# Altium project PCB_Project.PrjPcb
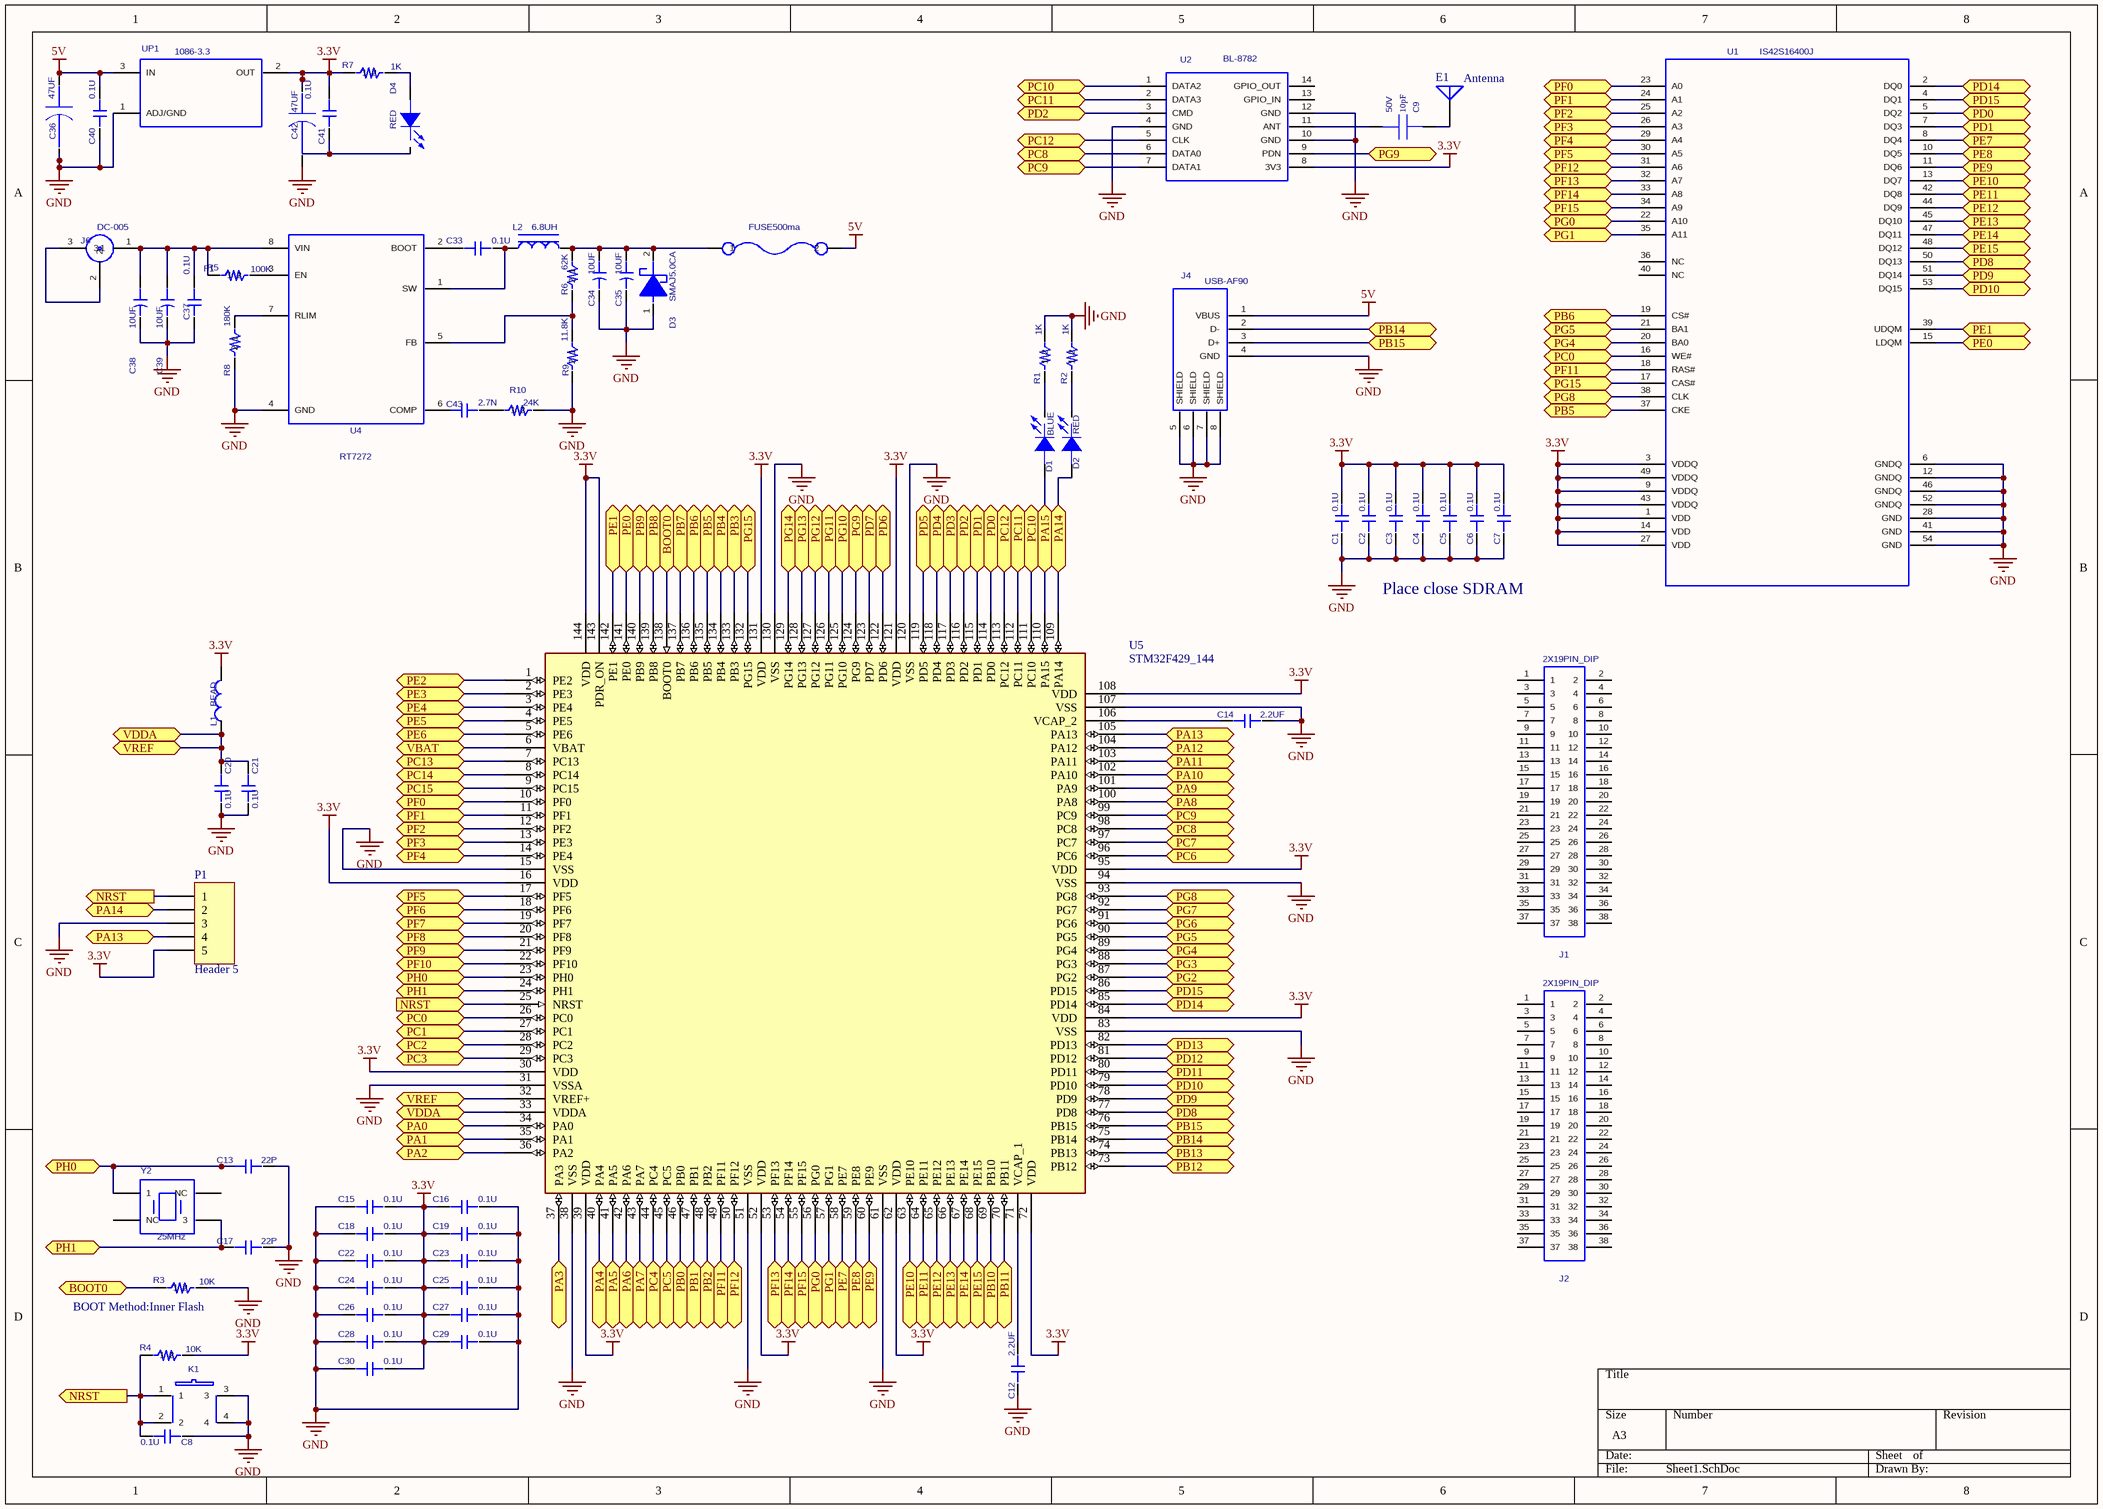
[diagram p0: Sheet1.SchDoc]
1 sheet, 69 parts. Net scope: flat (ports and power ports of the same name join across sheets).
Board files: e3.PcbDoc, Core3.PcbDoc, Core23.PcbDoc, PCB1.PcbDoc, NEW.PcbDoc

## Sheet Sheet1.SchDoc
size A3; DrawnBy: MARS

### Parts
C1  value 0.1U  [C_0603]  (hidden comment: C_0.1UF_0603)
C2  value 0.1U  [C_0603]  (hidden comment: C_0.1UF_0603)
C3  value 0.1U  [C_0603]  (hidden comment: C_0.1UF_0603)
C4  value 0.1U  [C_0603]  (hidden comment: C_0.1UF_0603)
C5  value 0.1U  [C_0603]  (hidden comment: C_0.1UF_0603)
C6  value 0.1U  [C_0603]  (hidden comment: C_0.1UF_0603)
C7  value 0.1U  [C_0603]  (hidden comment: C_0.1UF_0603)
C8  value 0.1U  [C_0603]  (hidden comment: C_0.1UF_0603)
C9  value 10pF  Voltage: 50V  [R_0603]  (hidden comment: CAP_NP)
C12  value 2.2UF  [CAP_0603_FIRE]  (hidden comment: C_2.2UF_0603)
C13  value 22P  [C_0603]  (hidden comment: C_22P_0603)
C14  value 2.2UF  [CAP_0603_FIRE]  (hidden comment: C_2.2UF_0603)
C15  value 0.1U  [C_0603]  (hidden comment: C_0.1UF_0603)
C16  value 0.1U  [C_0603]  (hidden comment: C_0.1UF_0603)
C17  value 22P  [C_0603]  (hidden comment: C_22P_0603)
C18  value 0.1U  [C_0603]  (hidden comment: C_0.1UF_0603)
C19  value 0.1U  [C_0603]  (hidden comment: C_0.1UF_0603)
C20  value 0.1U  [C_0603]  (hidden comment: C_0.1UF_0603)
C21  value 0.1U  [C_0603]  (hidden comment: C_0.1UF_0603)
C22  value 0.1U  [C_0603]  (hidden comment: C_0.1UF_0603)
C23  value 0.1U  [C_0603]  (hidden comment: C_0.1UF_0603)
C24  value 0.1U  [C_0603]  (hidden comment: C_0.1UF_0603)
C25  value 0.1U  [C_0603]  (hidden comment: C_0.1UF_0603)
C26  value 0.1U  [C_0603]  (hidden comment: C_0.1UF_0603)
C27  value 0.1U  [C_0603]  (hidden comment: C_0.1UF_0603)
C28  value 0.1U  [C_0603]  (hidden comment: C_0.1UF_0603)
C29  value 0.1U  [C_0603]  (hidden comment: C_0.1UF_0603)
C30  value 0.1U  [C_0603]  (hidden comment: C_0.1UF_0603)
C33  value 0.1U  [C_0603]  (hidden comment: C_0.1UF_0603)
C34  value 10UF  [AVX_B_3528-21]  (hidden comment: C+_10UF_B)
C35  value 10UF  [AVX_B_3528-21]  (hidden comment: C+_10UF_B)
C36  value 47UF  [EC_47UF_6.5X6.5]  (hidden comment: CAP+_47UF_6.5X6.5)
C37  value 0.1U  [C_0603]  (hidden comment: C_0.1UF_0603)
C38  value 10UF  [AVX_B_3528-21]  (hidden comment: C+_10UF_B)
C39  value 10UF  [AVX_B_3528-21]  (hidden comment: C+_10UF_B)
C40  value 0.1U  [C_0603]  (hidden comment: C_0.1UF_0603)
C41  value 0.1U  [C_0603]  (hidden comment: C_0.1UF_0603)
C42  value 47UF  [EC_47UF_6.5X6.5]  (hidden comment: CAP+_47UF_6.5X6.5)
C43  value 2.7N  [C_0603]  (hidden comment: C_2.7NF_0603)
D1  value BLUE  [LED_0603]  (hidden comment: LED_BLUE_0603)
D2  value RED  [LED_0603]  (hidden comment: LED_RED_0603)
D3  SMAJ5.0CA  [DO-214]
D4  value RED  [LED_0603]  (hidden comment: LED_RED_0603)
E1  Antenna  [PIN1]
F1  FUSE500MA  [C1812]
J1  2X19PIN_DIP  [2X19X2.54MM]
J2  2X19PIN_DIP  [2X19X2.54MM]
J4  USB-AF90  [USB-AF90]
J6  DC-005  [DC-005]
K1  KEY  [SW6.2/6.2-SMD]  (value not drawn)
L1  value BEAD  [R_0603]  (hidden comment: BEAD-0603)
L2  value 6.8UH  [GDCD4532]  (hidden comment: L_6.8UH_4532)
P1  Header 5  [HDR1X5]
R1  value 1K  [R_0603]  (hidden comment: R_1K_0603)
R2  value 1K  [R_0603]  (hidden comment: R_1K_0603)
R3  value 10K  [R_0603]  (hidden comment: R_10K_0603)
R4  value 10K  [R_0603]  (hidden comment: R_10K_0603)
R5  value 100K  [R_0603]  (hidden comment: R_100K_0603)
R6  value 62K  [R_0603]  (hidden comment: R_62K_0603)
R7  value 1K  [R_0603]  (hidden comment: R_1K_0603)
R8  value 180K  [R_0603]  (hidden comment: R_180K_0603)
R9  value 11.8K  [R_0603]  (hidden comment: R_11.8K_0603)
R10  value 24K  [R_0603]  (hidden comment: R_24K_0603)
U1  IS42S16400J  [TSOP-54]
U2  BL-8782  [BL-8782]
U4  RT7272  [RT7272]
U5  STM32F429_144  [429_144]
UP1  1086-3.3  [TO-252-2L]
Y2  value 25MHz  [CRYSTAL_25MHZ]  (hidden comment: CRYSTAL_25MHZ)

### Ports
BOOT0 (bidir), NRST (in), NRST (out), PA0 (bidir), PA1 (bidir), PA2 (bidir), PA3 (bidir), PA4 (bidir), PA5 (bidir), PA6 (bidir), PA7 (bidir), PA8 (bidir), PA9 (bidir), PA10 (bidir), PA11 (bidir), PA12 (bidir), PA13 (bidir), PA14 (bidir), PA15 (bidir), PB0 (bidir), PB1 (bidir), PB2 (bidir), PB3 (bidir), PB4 (bidir), PB5 (bidir), PB6 (bidir), PB7 (bidir), PB8 (bidir), PB9 (bidir), PB10 (bidir), PB11 (bidir), PB12 (bidir), PB13 (bidir), PB14 (bidir), PB15 (bidir), PC0 (bidir), PC1 (bidir), PC2 (bidir), PC3 (bidir), PC4 (bidir), PC5 (bidir), PC6 (bidir), PC7 (bidir), PC8 (bidir), PC9 (bidir), PC10 (bidir), PC11 (bidir), PC12 (bidir), PC13 (bidir), PC14 (bidir), PC15 (bidir), PD0 (bidir), PD1 (bidir), PD2 (bidir), PD3 (bidir), PD4 (bidir), PD5 (bidir), PD6 (bidir), PD7 (bidir), PD8 (bidir), PD9 (bidir), PD10 (bidir), PD11 (bidir), PD12 (bidir), PD13 (bidir), PD14 (bidir), PD15 (bidir), PE0 (bidir), PE1 (bidir), PE2 (bidir), PE3 (bidir), PE4 (bidir), PE5 (bidir), PE6 (bidir), PE7 (bidir), PE8 (bidir), PE9 (bidir), PE10 (bidir), PE11 (bidir), PE12 (bidir), PE13 (bidir), PE14 (bidir), PE15 (bidir), PF0 (bidir), PF1 (bidir), PF2 (bidir), PF3 (bidir), PF4 (bidir), PF5 (bidir), PF6 (bidir), PF7 (bidir), PF8 (bidir), PF9 (bidir), PF10 (bidir), PF11 (bidir), PF12 (bidir), PF13 (bidir), PF14 (bidir), PF15 (bidir), PG0 (bidir), PG1 (bidir), PG2 (bidir), PG3 (bidir), PG4 (bidir), PG5 (bidir), PG6 (bidir), PG7 (bidir), PG8 (bidir), PG9 (bidir), PG10 (bidir), PG11 (bidir), PG12 (bidir), PG13 (bidir), PG14 (bidir), PG15 (bidir), PH0 (bidir), PH1 (bidir), VBAT, VDDA, VREF

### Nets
3.3V: C1.2 C2.2 C3.2 C4.2 C5.2 C6.2 C7.2 C15.1 C16.2 C18.1 C19.2 C22.1 C23.2 C24.1 C25.2 C26.1 C27.2 C28.1 C29.2 C30.1 C41.1 C42.1 L1.2 P1.5 R4.2 R7.1 U1.1(VDD) U1.3(VDDQ) U1.9(VDDQ) U1.14(VDD) U1.27(VDD) U1.43(VDDQ) U1.49(VDDQ) U2.8(3V3) U5.16(VDD) U5.30(VDD) U5.39(VDD) U5.52(VDD) U5.62(VDD) U5.72(VDD) U5.84(VDD) U5.95(VDD) U5.108(VDD) U5.121(VDD) U5.131(VDD) U5.143(PDR_ON) U5.144(VDD) UP1.2(OUT)
5V: C36.1 C40.1 F1.2 J4.1(VBUS) UP1.3(IN)
GND: C1.1 C2.1 C3.1 C4.1 C5.1 C6.1 C7.1 C8.1 C12.1 C13.2 C14.2 C15.2 C16.1 C17.2 C18.2 C19.1 C20.1 C21.1 C22.2 C23.1 C24.2 C25.1 C26.2 C27.1 C28.2 C29.1 C30.2 C34.2(-) C35.2(-) C36.2 C37.2 C38.2(-) C39.2(-) C40.2 C42.2 D3.1(+) J4.4(GND) J4.5(SHIELD) J4.6(SHIELD) J4.7(SHIELD) J4.8(SHIELD) K1.3 K1.4 P1.3 R1.2 R2.2 R3.2 R8.2 R9.2 R10.2 U1.6(GNDQ) U1.12(GNDQ) U1.28(GND) U1.41(GND) U1.46(GNDQ) U1.52(GNDQ) U1.54(GND) U2.4(GND) U2.10(GND) U2.12(GND) U4.4(GND) U5.15(VSS) U5.31(VSSA) U5.38(VSS) U5.51(VSS) U5.61(VSS) U5.83(VSS) U5.94(VSS) U5.107(VSS) U5.120(VSS) U5.130(VSS) UP1.1(ADJ/GND)
NetC8_2: C8.2 K1.1 K1.2 P1.1 R4.1 U5.25(NRST) ; port NRST
NetC9_1: C9.1 E1.1(A)
NetC9_2: C9.2 U2.11(ANT)
NetC12_2: C12.2 U5.71(VCAP_1)
NetC13_1: C13.1 U5.23(PH0) Y2.1 ; port PH0
NetC14_1: C14.1 U5.106(VCAP_2)
NetC17_1: C17.1 U5.24(PH1) Y2.3 ; port PH1
NetC20_2: C20.2 C21.2 L1.1 U5.32(VREF+) U5.33(VDDA) ; port VREF, port VDDA
NetC33_1: C33.1 L2.1 U4.1(SW)
NetC33_2: C33.2 U4.2(BOOT)
NetC34_1: C34.1(+) C35.1(+) D3.2(-) F1.1 L2.2 R6.1
NetC37_1: C37.1 C38.1(+) C39.1(+) J6.1 R5.1 U4.8(VIN)
NetC41_2: C41.2 D4.K(CATHODE)
NetC43_2: C43.2 R10.1
NetD1_A: D1.A(ANODE) U5.110(PA15) ; port PA15
NetD1_K: D1.K(CATHODE) R1.1
NetD2_A: D2.A(ANODE) P1.2 U5.109(PA14) ; port PA14
NetD2_K: D2.K(CATHODE) R2.1
NetD4_A: D4.A(ANODE) R7.2
NetJ4_2: J4.2(D-) U5.75(PB14) ; port PB14
NetJ4_3: J4.3(D+) U5.76(PB15) ; port PB15
NetJ6_2: J6.2 J6.3
NetP1_4: P1.4 U5.105(PA13) ; port PA13
NetR3_1: R3.1 U5.138(BOOT0) ; port BOOT0
NetR5_2: R5.2 U4.3(EN)
NetR6_2: R6.2 R9.1 U4.5(FB)
NetR8_1: R8.1 U4.7(RLIM)
NetU1_2: U1.2(DQ0) U5.85(PD14) ; port PD14
NetU1_4: U1.4(DQ1) U5.86(PD15) ; port PD15
NetU1_5: U1.5(DQ2) U5.114(PD0) ; port PD0
NetU1_7: U1.7(DQ3) U5.115(PD1) ; port PD1
NetU1_8: U1.8(DQ4) U5.58(PE7) ; port PE7
NetU1_10: U1.10(DQ5) U5.59(PE8) ; port PE8
NetU1_11: U1.11(DQ6) U5.60(PE9) ; port PE9
NetU1_13: U1.13(DQ7) U5.63(PE10) ; port PE10
NetU1_15: U1.15(LDQM) U5.141(PE0) ; port PE0
NetU1_16: U1.16(WE#) U5.26(PC0) ; port PC0
NetU1_17: U1.17(CAS#) U5.132(PG15) ; port PG15
NetU1_18: U1.18(RAS#) U5.49(PF11) ; port PF11
NetU1_19: U1.19(CS#) U5.136(PB6) ; port PB6
NetU1_20: U1.20(BA0) U5.89(PG4) ; port PG4
NetU1_21: U1.21(BA1) U5.90(PG5) ; port PG5
NetU1_22: U1.22(A10) U5.56(PG0) ; port PG0
NetU1_23: U1.23(A0) U5.10(PF0) ; port PF0
NetU1_24: U1.24(A1) U5.11(PF1) ; port PF1
NetU1_25: U1.25(A2) U5.12(PF2) ; port PF2
NetU1_26: U1.26(A3) U5.13(PE3) ; port PF3
NetU1_29: U1.29(A4) U5.14(PE4) ; port PF4
NetU1_30: U1.30(A5) U5.17(PF5) ; port PF5
NetU1_31: U1.31(A6) U5.50(PF12) ; port PF12
NetU1_32: U1.32(A7) U5.53(PF13) ; port PF13
NetU1_33: U1.33(A8) U5.54(PF14) ; port PF14
NetU1_34: U1.34(A9) U5.55(PF15) ; port PF15
NetU1_35: U1.35(A11) U5.57(PG1) ; port PG1
NetU1_37: U1.37(CKE) U5.135(PB5) ; port PB5
NetU1_38: U1.38(CLK) U5.93(PG8) ; port PG8
NetU1_39: U1.39(UDQM) U5.142(PE1) ; port PE1
NetU1_42: U1.42(DQ8) U5.64(PE11) ; port PE11
NetU1_44: U1.44(DQ9) U5.65(PE12) ; port PE12
NetU1_45: U1.45(DQ10) U5.66(PE13) ; port PE13
NetU1_47: U1.47(DQ11) U5.67(PE14) ; port PE14
NetU1_48: U1.48(DQ12) U5.68(PE15) ; port PE15
NetU1_50: U1.50(DQ13) U5.77(PD8) ; port PD8
NetU1_51: U1.51(DQ14) U5.78(PD9) ; port PD9
NetU1_53: U1.53(DQ15) U5.79(PD10) ; port PD10
NetU2_1: U2.1(DATA2) U5.111(PC10) ; port PC10
NetU2_2: U2.2(DATA3) U5.112(PC11) ; port PC11
NetU2_3: U2.3(CMD) U5.116(PD2) ; port PD2
NetU2_5: U2.5(CLK) U5.113(PC12) ; port PC12
NetU2_6: U2.6(DATA0) U5.98(PC8) ; port PC8
NetU2_7: U2.7(DATA1) U5.99(PC9) ; port PC9
NetU2_9: U2.9(PDN) U5.124(PG9) ; port PG9
NetU5_1: U5.1(PE2) ; port PE2
NetU5_2: U5.2(PE3) ; port PE3
NetU5_3: U5.3(PE4) ; port PE4
NetU5_4: U5.4(PE5) ; port PE5
NetU5_5: U5.5(PE6) ; port PE6
NetU5_6: U5.6(VBAT) ; port VBAT
NetU5_7: U5.7(PC13) ; port PC13
NetU5_8: U5.8(PC14) ; port PC14
NetU5_9: U5.9(PC15) ; port PC15
NetU5_18: U5.18(PF6) ; port PF6
NetU5_19: U5.19(PF7) ; port PF7
NetU5_20: U5.20(PF8) ; port PF8
NetU5_21: U5.21(PF9) ; port PF9
NetU5_22: U5.22(PF10) ; port PF10
NetU5_27: U5.27(PC1) ; port PC1
NetU5_28: U5.28(PC2) ; port PC2
NetU5_29: U5.29(PC3) ; port PC3
NetU5_34: U5.34(PA0) ; port PA0
NetU5_35: U5.35(PA1) ; port PA1
NetU5_36: U5.36(PA2) ; port PA2
NetU5_37: U5.37(PA3) ; port PA3
NetU5_40: U5.40(PA4) ; port PA4
NetU5_41: U5.41(PA5) ; port PA5
NetU5_42: U5.42(PA6) ; port PA6
NetU5_43: U5.43(PA7) ; port PA7
NetU5_44: U5.44(PC4) ; port PC4
NetU5_45: U5.45(PC5) ; port PC5
NetU5_46: U5.46(PB0) ; port PB0
NetU5_47: U5.47(PB1) ; port PB1
NetU5_48: U5.48(PB2) ; port PB2
NetU5_69: U5.69(PB10) ; port PB10
NetU5_70: U5.70(PB11) ; port PB11
NetU5_73: U5.73(PB12) ; port PB12
NetU5_74: U5.74(PB13) ; port PB13
NetU5_80: U5.80(PD11) ; port PD11
NetU5_81: U5.81(PD12) ; port PD12
NetU5_82: U5.82(PD13) ; port PD13
NetU5_87: U5.87(PG2) ; port PG2
NetU5_88: U5.88(PG3) ; port PG3
NetU5_91: U5.91(PG6) ; port PG6
NetU5_92: U5.92(PG7) ; port PG7
NetU5_96: U5.96(PC6) ; port PC6
NetU5_97: U5.97(PC7) ; port PC7
NetU5_100: U5.100(PA8) ; port PA8
NetU5_101: U5.101(PA9) ; port PA9
NetU5_102: U5.102(PA10) ; port PA10
NetU5_103: U5.103(PA11) ; port PA11
NetU5_104: U5.104(PA12) ; port PA12
NetU5_117: U5.117(PD3) ; port PD3
NetU5_118: U5.118(PD4) ; port PD4
NetU5_119: U5.119(PD5) ; port PD5
NetU5_122: U5.122(PD6) ; port PD6
NetU5_123: U5.123(PD7) ; port PD7
NetU5_125: U5.125(PG10) ; port PG10
NetU5_126: U5.126(PG11) ; port PG11
NetU5_127: U5.127(PG12) ; port PG12
NetU5_128: U5.128(PG13) ; port PG13
NetU5_129: U5.129(PG14) ; port PG14
NetU5_133: U5.133(PB3) ; port PB3
NetU5_134: U5.134(PB4) ; port PB4
NetU5_137: U5.137(PB7) ; port PB7
NetU5_139: U5.139(PB8) ; port PB8
NetU5_140: U5.140(PB9) ; port PB9

Not connected (* = marked no-connect by the designer): C43 1; J1 1 2 3 4 5 6 7 8 9 10 11 12 13 14 15 16 17 18 19 20 21 22 23 24 25 26 27 28 29 30 31 32 33 34 35 36 37 38; J2 1 2 3 4 5 6 7 8 9 10 11 12 13 14 15 16 17 18 19 20 21 22 23 24 25 26 27 28 29 30 31 32 33 34 35 36 37 38; U1 36(NC) 40(NC); U2 13(GPIO_IN) 14(GPIO_OUT); U4 6(COMP); Y2 2(NC) 4(NC)

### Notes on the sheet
- Place close SDRAM
- (near R3) BOOT Method:Inner Flash

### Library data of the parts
C9 = CAP_NP: 0603, X7R, 50V, 10%(K); Partname: 贴片电容  0603; Mfr: Fenghua; Mfr_Part_Number: 0603B104K500NT; Part_Number: CA100039-01; Spec: 100nF/50V 10%(K) X7R,0603B104K500NT(风华); Remarks: Checked; Gtech_Number: 50306031003K50V01; Source_Path: D:\CADENCELIB\CAPTURELIB\LC_PASSIVE.OLB
D3 = SMAJ5.0CA: SMAJ5.0CA-E3/61 400W 5V
E1 = Antenna: Generic Antenna
F1 = FUSE500MA: Assembly: SMD
P1 = Header 5: Header, 5-Pin
U2 = BL-8782: Value: HC-05
UP1 = 1086-3.3: Manufacturer #1: AMS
